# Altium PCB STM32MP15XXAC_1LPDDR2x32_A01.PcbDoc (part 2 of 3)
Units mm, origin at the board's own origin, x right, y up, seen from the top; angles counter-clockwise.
Board outline 89 x 120 mm, 6 copper layers (Top Layer, Signal Layer 1, Signal Layer 2, Signal Layer 3, Signal Layer 4, Bottom Layer), stack 1.556 mm thick; 87 components, 99 nets, 861 pads, 454 vias.
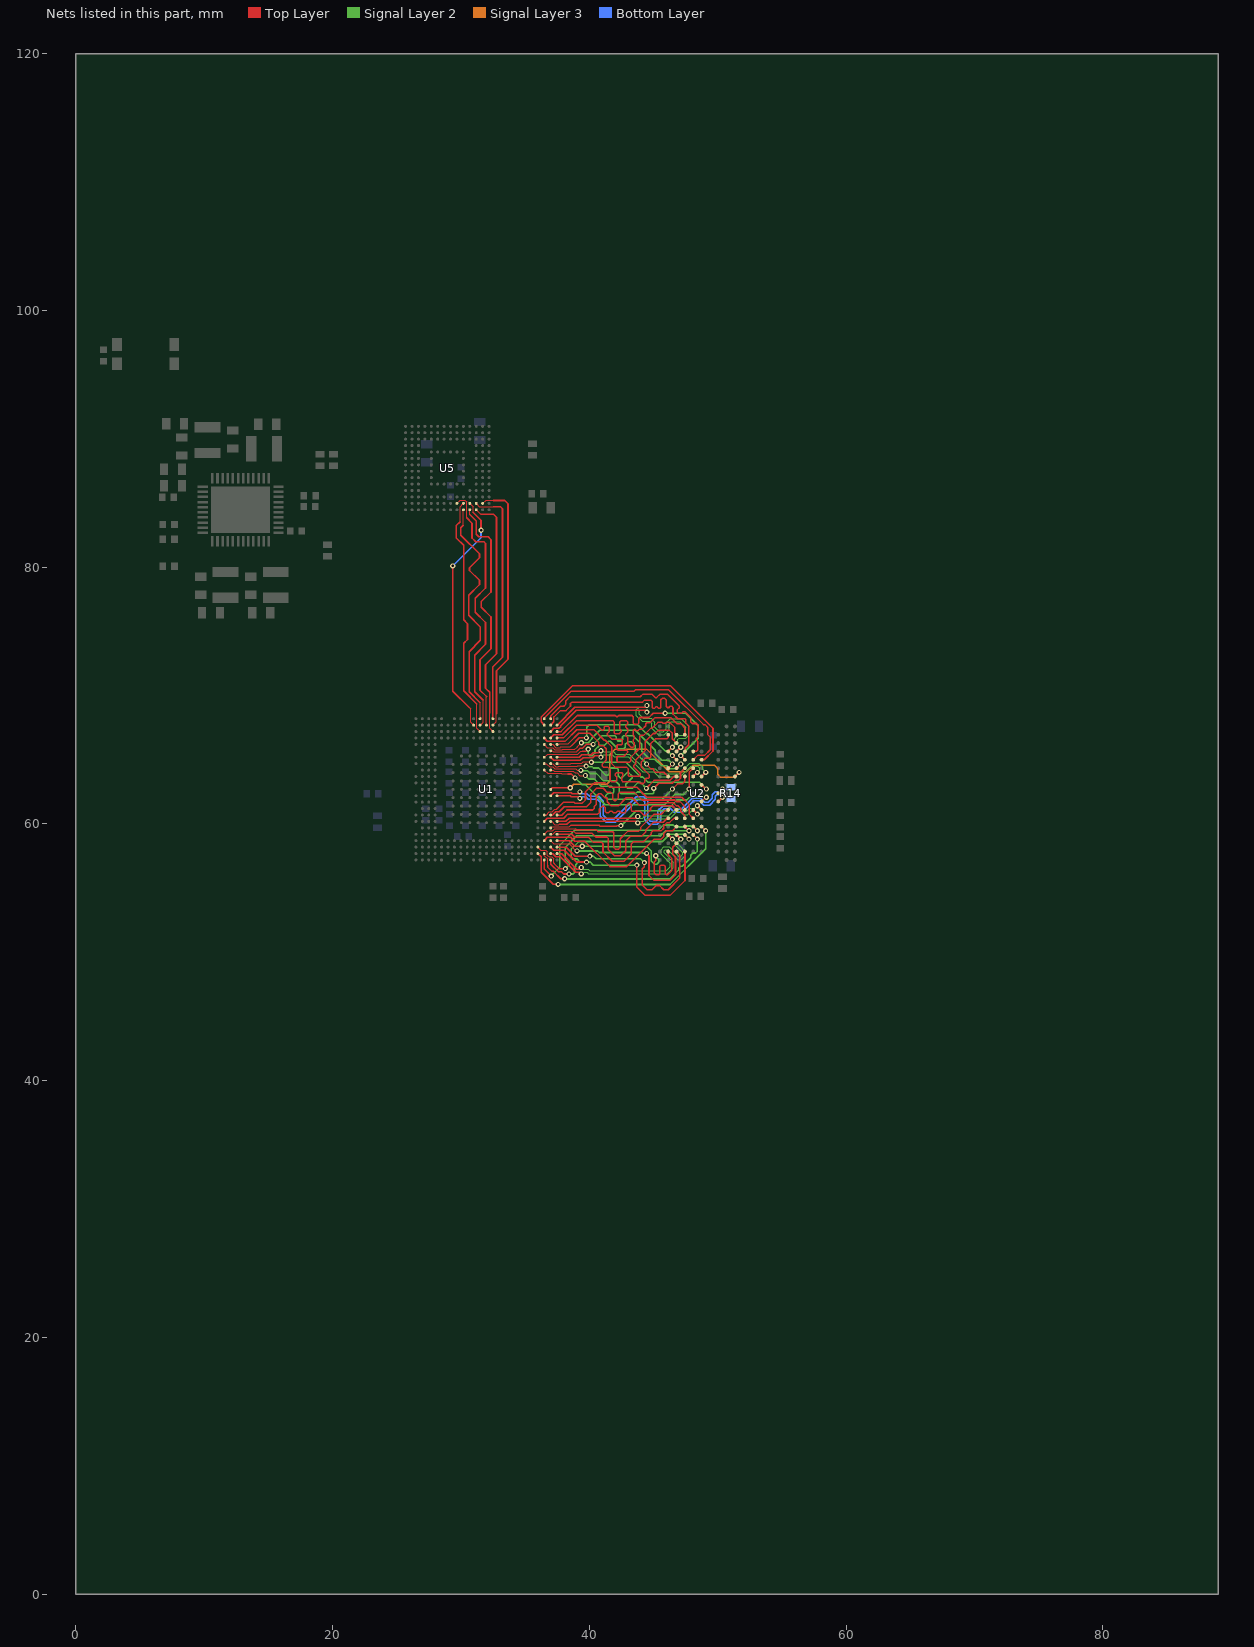
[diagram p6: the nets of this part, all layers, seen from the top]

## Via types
v1: diameter 0.4, hole 0.2, Top Layer to Bottom Layer, tented both sides, 265 vias
v2: diameter 0.6, hole 0.3, Top Layer to Bottom Layer, tented both sides, 102 vias
v3: diameter 0.25, hole 0.1, Top Layer to Signal Layer 1, tented top, 82 vias
v4: diameter 0.25, hole 0.1, Top Layer to Signal Layer 1, tented both sides, 5 vias

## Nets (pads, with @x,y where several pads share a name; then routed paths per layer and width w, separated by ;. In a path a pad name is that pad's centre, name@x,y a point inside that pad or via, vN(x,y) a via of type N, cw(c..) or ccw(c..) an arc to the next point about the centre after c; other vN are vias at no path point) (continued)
DDR_CLK_N: R14.2 U1.N23 U2.H3 | length 20
  Top Layer w0.1: U1.N23@37.5,62.2 38.521,62.2 38.591,62.13 39.141,62.13 v1(39.277,61.994) ; U2.H3@50.05,61.75 v1(50.375,62.075)
  Bottom Layer w0.1: v1@39.31,61.996 39.447,62.132 39.728,62.132 39.938,61.922 40.645,61.922 40.876,61.691 40.876,60.594 41.32,60.15 42.02,60.15 43.764,61.894 44.143,61.894 44.317,61.721 44.317,60.328 44.662,59.983 45.313,59.983 45.587,60.257 45.587,60.926 45.848,61.187 46.364,61.187 46.638,60.913 47.254,60.913 48.134,61.794 48.595,61.794 48.91,61.478 49.369,61.478 49.8,61.909 49.8,62.18 49.917,62.297 50.161,62.297 v1@50.377,62.081 ; v1@50.377,62.077 50.898,62.077 R14.2@51.025,61.95
DDR_CLK_P: R14.1 U1.N22 U2.J3 | length 20.7
  Top Layer w0.1: U1.N22@37,62.2 37.245,62.445 37.655,62.445 37.67,62.43 38.616,62.43 38.686,62.36 39.137,62.36 v1(39.277,62.5) ; U2.J3@50.05,62.4 v1(50.375,62.725)
  Bottom Layer w0.1: v1@39.281,62.504 39.422,62.362 39.823,62.362 40.027,62.159 40.733,62.159 41.106,61.786 41.106,60.689 41.415,60.38 41.925,60.38 43.669,62.124 44.238,62.124 44.547,61.816 44.547,60.424 44.757,60.213 45.218,60.213 45.357,60.352 45.357,61.022 45.753,61.417 46.46,61.417 46.734,61.143 47.159,61.143 48.039,62.024 48.69,62.024 49.006,61.708 49.274,61.708 49.57,62.004 49.57,62.275 49.822,62.527 50.174,62.527 50.373,62.725 v1(50.375,62.725) 50.9,62.725 R14.1@51.025,62.85
DDR_CSN: U1.M22 U2.L1 | length 19.5
  Top Layer w0.12: U1.M22@37,62.7 37.121,62.821 v1(38.521,62.821) v1@38.571,62.821 ; U2.L1@51.35,63.7 v1@51.667,64.017
  Signal Layer 3 w0.127: v1@38.518,62.813 38.523,62.819 38.799,63.094 41.364,63.094 41.592,63.322 41.592,65.4 42.025,65.834 44.462,65.834 46.236,64.059 47.582,64.059 48.106,64.583 49.751,64.583 50.008,64.326 50.008,63.867 50.221,63.654 51.311,63.654 v1@51.678,64.021
  other v1: 51.675,64.025
DDR_DQ0: U1.E22 U2.N8 | length 12.2
  Top Layer w0.09: U1.E22@37,66.2 37.154,66.2 37.399,65.955 37.725,65.955 37.8,66.03 38.535,66.03 38.615,66.11
  Top Layer w0.12: 38.631,66.11 39.231,66.71 v1(39.775,66.71) ; v1(46.475,65.325) U2.N8@46.8,65
  Signal Layer 2 w0.127: v1@39.804,66.71 39.804,67.535 40.003,67.733 ; 40.003,67.737 43.77,67.737 44.466,67.04 44.568,67.04 45.919,65.689 46.113,65.689 v1@46.476,65.326
DDR_DQ1: U1.F22 U2.M8 | length 13.2
  Top Layer w0.09: U1.F22@37,65.7 37.115,65.7 37.2,65.615 38.065,65.615 38.085,65.635 39.012,65.635 39.117,65.74
  Top Layer w0.12: 39.117,65.74 39.284,65.907 39.487,65.907 39.775,66.195 v1(40.3,66.195) ; U2.M8@46.8,64.35 v1(47.125,64.675)
  Signal Layer 2 w0.127: v1@40.302,66.196 40.99,66.884 41.992,66.884 42.095,66.78 42.095,66.621 42.247,66.469 42.479,66.469 42.591,66.582 42.591,66.783 42.693,66.884 43.412,66.884 43.725,66.571 ; 43.726,66.573 44.096,66.202 44.096,65.669 44.715,65.05 45.115,65.05 45.634,64.532 ; 45.634,64.533 46.054,64.533 46.277,64.311 46.768,64.311 47.128,64.671 v1@47.129,64.672
DDR_DQ2: U1.H21 U2.M7 | length 13.7
  Top Layer w0.09: U1.H21@36.5,64.7 36.654,64.7 36.909,64.445 37.168,64.445 37.328,64.285 37.672,64.285 37.692,64.305 38.945,64.305 39.075,64.175 v1(39.355,64.175)
  Top Layer w0.12: v1@45.02,62.773 45.023,62.776 45.416,63.17 46.47,63.17 46.69,63.39 46.928,63.39 47.11,63.571 47.11,64.01 U2.M7@47.45,64.35
  Signal Layer 2 w0.127: v1(39.355,64.175) 39.388,64.142 39.868,64.142 40.081,63.929 40.562,63.929 41.119,63.371 42.029,63.371 42.349,63.051 42.349,62.492 42.483,62.358 43.605,62.358 43.743,62.497 44.009,62.497 44.148,62.358 44.949,62.358 45.026,62.435 v1(45.025,62.775)
DDR_DQ3: U1.E21 U2.M9 | length 12.5
  Top Layer w0.09: U1.E21@36.5,66.2 36.75,65.95 ; 36.751,65.95 37.163,65.95 37.328,65.785 37.89,65.785 37.93,65.825 38.89,65.825 39.052,65.988
  Top Layer w0.12: 39.052,65.988 v1(39.395,66.33) ; U2.M9@46.16,64.35 46.48,64.67 v1@46.485,64.675
  Signal Layer 2 w0.127: v1@39.397,66.331 39.915,66.331 40.222,66.637 40.222,66.721 ; 40.231,66.729 40.813,67.311 43.591,67.311 45.149,65.753 45.149,65.486 45.674,64.961 45.975,64.961 46.199,64.962 46.481,64.681 v1@46.487,64.675
  other v1: 46.475,64.675
DDR_DQ4: U1.J21 U2.M6 | length 14.7
  Top Layer w0.09: U1.J21@36.5,64.2 36.755,63.945 37.82,63.945 37.87,63.895 38.335,63.895
  Top Layer w0.12: 38.335,63.895 38.6,63.895 v1@38.899,63.596 ; v1(47.775,62.725) 47.775,64.027 U2.M6@48.1,64.35 U2.M6@48.101,64.353
  Signal Layer 2 w0.127: v1@38.899,63.598 38.901,63.597 39.451,63.046 39.721,63.046 ; 39.724,63.04 41.26,61.504 45.869,61.504 46.663,62.299 47.349,62.299 v1(47.775,62.725) v1@47.776,62.725
  other v1: 38.9,63.596
DDR_DQ5: U1.J22 U2.L7 | length 13.9
  Top Layer w0.09: U1.J22@37,64.19 37.183,64.19 37.258,64.115 38.77,64.115 38.9,63.985 39.055,63.985 39.265,63.775 v1(39.7,63.775)
  Top Layer w0.12: v1@46.464,62.722 46.47,62.729 46.866,63.125 47.267,63.125 47.45,63.308 U2.L7@47.45,63.698
  Signal Layer 2 w0.127: v1@39.702,63.776 39.976,63.502 40.385,63.502 40.942,62.944 41.722,62.944 41.922,62.744 41.922,62.493 41.832,62.403 41.481,62.403 41.296,62.218 41.296,62.072 41.437,61.931 45.692,61.931 46.48,62.719 v1@46.486,62.725
  other v1: 46.475,62.725
DDR_DQ6: U1.H22 U2.L8 | length 13.9
  Top Layer w0.09: U1.H22@37,64.7 37.154,64.7 37.399,64.455 37.601,64.455 37.646,64.5 39.085,64.5 39.12,64.535 39.725,64.535 v1(39.755,64.505)
  Top Layer w0.12: v1@44.445,62.791 45.044,63.39 46.278,63.39 46.588,63.7 U2.L8@46.8,63.7
  Signal Layer 2 w0.127: v1(39.755,64.505) 39.814,64.447 40.25,64.447 40.335,64.362 ; 40.338,64.358 40.737,64.358 41.296,63.798 41.449,63.798 41.561,63.91 41.561,64.242 41.676,64.357 42.164,64.357 42.252,64.268 42.252,63.755 42.42,63.587 42.536,63.587 42.957,64.007 43.063,64.007 43.345,63.725 43.345,63.6 42.848,63.103 42.848,62.945 43.001,62.792 43.365,62.792 43.804,63.231 44.001,63.231 v1@44.447,62.785
  other v1: 44.45,62.775
DDR_DQ7: U1.G21 U2.L9 | length 13
  Top Layer w0.09: U1.G21@36.515,65.2 36.76,65.445 39.12,65.445 39.34,65.665 39.46,65.665
  Top Layer w0.12: 39.46,65.665 39.76,65.665 v1(39.925,65.83) ; v1@44.48,64.61 44.775,64.315 44.95,64.315 45.04,64.226 45.04,64.159 45.163,64.036 45.813,64.036 U2.L9@46.15,63.7
  Signal Layer 2 w0.127: v1@39.927,65.826 39.927,65.426 40.027,65.326 40.252,65.326 40.452,65.526 40.452,65.776 40.809,66.133 41.193,66.133 41.502,66.442 41.647,66.442 42.231,65.858 42.699,65.858 42.817,65.976 42.817,66.204 43.006,66.393 43.3,66.393 43.594,66.099 43.594,65.568 44.481,64.681 v1@44.487,64.675
  other v1: 44.475,64.675
DDR_DQ8: U1.T21 U2.F6 | length 14.7
  Top Layer w0.09: U1.T21@36.5,60.7 36.654,60.7 36.899,60.945 37.116,60.945 37.316,61.145 37.455,61.145 37.493,61.183
  Top Layer w0.12: 37.493,61.183 38.02,61.71 38.8,61.71 38.9,61.61 39.442,61.61 39.709,61.877 ; 39.711,61.878 39.711,62.511 ; 39.712,62.512 40.398,63.198 41.26,63.198 41.58,62.878 43.701,62.878 ; 43.699,62.878 44.487,62.09 47.197,62.09 ; 47.199,62.09 47.776,61.513 47.776,60.773 U2.F6@48.1,60.45
DDR_DQ9: U1.U21 U2.G8 | length 13.3
  Top Layer w0.1: U1.U21@36.5,60.2 36.75,60.45 38.01,60.45
  Top Layer w0.12: 38.01,60.45 38.33,60.77 40.666,60.77 40.799,60.903 ; 40.801,60.905 40.801,61.172 41.027,61.398 41.136,61.398 41.249,61.286 41.249,60.965 41.344,60.87 41.509,60.87 41.628,60.99 41.778,60.99 41.897,60.87 42.078,60.87 42.197,60.99 42.384,60.99 42.503,60.87 42.764,60.87 42.836,60.942 42.836,61.398 43.056,61.618 43.177,61.618 43.258,61.537 43.258,61.097 43.359,60.996 43.954,60.996 44.254,60.696 44.383,60.696 44.772,61.085 44.772,61.23 44.972,61.43 46.469,61.43 ; 46.47,61.43 U2.G8@46.8,61.1
DDR_DQ10: U1.T22 U2.G7 | length 13.5
  Top Layer w0.09: U1.T22@37,60.7 37.154,60.7
  Top Layer w0.1: 37.149,60.704 37.405,60.96 37.67,60.96
  Top Layer w0.12: 37.67,60.96 38.06,61.35 39.791,61.35 40.133,61.692 ; 40.131,61.704 40.131,62.336 40.573,62.778 41.086,62.778 41.406,62.458 41.691,62.458 41.819,62.331 41.819,61.961 41.95,61.83 42.079,61.83 42.246,61.996 42.246,62.329 42.375,62.458 43.525,62.458 44.113,61.87 46.65,61.87 ; 46.652,61.87 46.77,61.751 47.064,61.751 47.449,61.367 U2.G7@47.45,61.1
DDR_DQ11: U1.W21 U2.G9 | length 12.9
  Top Layer w0.09: U1.W21@36.5,59.2 36.755,59.455 37.168,59.455 37.328,59.615 38.94,59.615
  Top Layer w0.12: 38.94,59.615 38.995,59.56 40.525,59.56 40.678,59.407 41.826,59.407 41.915,59.318 41.915,58.169 42.042,58.043 42.284,58.043 42.421,58.18 42.421,58.843 43.026,59.449 43.871,59.449 44,59.577 44,59.719 45.039,60.758 ; 45.041,60.76 45.61,60.76 45.95,61.1 U2.G9@46.15,61.1
DDR_DQ12: U1.W23 U2.F8 | length 12.6
  Top Layer w0.1: U1.W23@37.5,59.2 38.635,59.2 38.875,58.96
  Top Layer w0.12: 38.875,58.96 39.937,58.96 40.33,58.567 40.971,58.567 41.075,58.462 41.075,57.816 41.787,57.104 42.715,57.104 43.261,57.65 43.261,58.415 43.455,58.609 44.219,58.609 44.84,59.229 44.84,59.348 44.952,59.46 45.264,59.46 45.598,59.46 ; 45.597,59.46 45.809,59.672 45.809,59.869 46.049,60.11 46.26,60.11 46.6,60.45 U2.F8@46.8,60.45
DDR_DQ13: U1.T23 U2.F7 | length 13
  Top Layer w0.1: U1.T23@37.5,60.7 37.875,60.7 38.03,60.855
  Top Layer w0.12: 38.03,60.855 38.265,61.09 40.273,61.09 40.381,61.198 40.381,61.346 40.553,61.518 40.553,62.163 40.747,62.358 40.912,62.358 41.232,62.038 41.323,62.038 41.399,61.962 41.399,61.73 41.719,61.41 42.255,61.41 42.882,62.037 43.351,62.038 43.939,61.45 44.395,61.45 44.595,61.65 46.558,61.65 ; 46.561,61.65 46.801,61.41 46.928,61.41 47.121,61.216 47.121,60.989 47.448,60.663 ; U2.F7@47.45,60.45 47.45,60.661
DDR_DQ14: U1.W22 U2.F9 | length 12.3
  Top Layer w0.09: U1.W22@37,59.2 37.154,59.2 37.399,59.445 38.8,59.445 38.965,59.28
  Top Layer w0.12: 38.965,59.28 40.211,59.28 40.504,58.987 41.375,58.987 41.495,58.866 41.495,57.99 41.961,57.524 42.442,57.524 42.841,57.923 42.841,58.669 43.2,59.029 44.045,59.029 44.42,59.403 44.42,59.545 45.01,60.135 45.764,60.135 46.077,60.448 46.15,60.448 U2.F9@46.174,60.448
DDR_DQ15: U1.Y21 U2.E8 | length 12.8
  Top Layer w0.1: U1.Y21@36.5,58.7 36.75,58.95 38.55,58.95 38.86,58.64
  Top Layer w0.12: 38.86,58.64 39.659,58.64 ; 39.659,58.638 41.613,56.684 42.924,56.684 ; 42.925,56.683 45.072,58.83 45.618,58.83 45.81,59.021 45.81,59.27 46.005,59.465 46.465,59.465 U2.E8@46.8,59.8
DDR_DQ16: U1.B22 U2.P7 | length 17
  Top Layer w0.1: U1.B22@37.003,67.703 37.25,67.95 37.25,68.34
  Top Layer w0.12: 37.25,68.34 37.761,68.838 38.199,68.838 38.543,69.182 38.543,69.391 38.652,69.5 44.152,69.5 44.302,69.65 44.8,69.65 44.9,69.551 44.9,69.099 44.992,69.007 45.083,69.007 45.197,69.121 45.295,69.121 45.409,69.007 45.518,69.007 45.579,69.067 45.579,69.67 45.709,69.8 45.86,69.8 46.007,69.654 46.007,69.141 46.075,69.073 46.221,69.073 46.313,69.164 46.427,69.164 46.526,69.065 46.526,68.568 ; 46.526,68.567 46.89,68.202 47.454,68.202 47.532,68.125 47.532,67.86 47.76,67.632 47.76,66.171 47.48,65.892 U2.P7@47.48,65.655
DDR_DQ17: U1.D22 U2.T7 | length 18
  Top Layer w0.1: U1.D22@37,66.7 37.25,66.95 37.66,66.95
  Top Layer w0.12: 37.66,66.95 37.905,66.95 38.984,68.029 ; 38.985,68.03 41.863,68.03 41.967,67.927 41.967,67.089 42.026,67.03 42.332,67.03 42.478,67.177 42.478,67.301 42.39,67.389 42.39,67.96 42.46,68.03 42.916,68.03 43.012,67.934 43.012,67.839 42.84,67.667 42.84,67.549 43.008,67.381 43.008,67.175 42.831,66.999 42.831,66.896 42.999,66.729 42.999,66.25 43.282,65.967 43.415,65.967 43.519,66.071 43.519,66.334 43.418,66.435 43.418,66.548 ; 43.42,66.552 43.519,66.65 43.519,66.827 43.42,66.926 43.42,67.278 43.503,67.361 43.588,67.361 43.69,67.259 43.772,67.259 ; 43.779,67.26 43.882,67.363 44.108,67.363 44.403,67.658 44.403,67.813 44.485,67.895 44.746,67.895 45.016,68.167 ; 45.015,68.168 45.114,68.267 46.374,68.267 ; 46.374,68.267 46.841,67.8 47.14,67.8 47.45,67.49 U2.T7@47.45,66.95
DDR_DQ18: U1.D23 U2.T8 | length 17.5
  Top Layer w0.12: U1.D23@37.5,66.7 38.007,66.7 38.983,67.675 40.622,67.675 40.981,67.317 41.082,67.317 ; 41.09,67.318 41.16,67.388 41.16,67.547 41.223,67.61 41.483,67.61 41.548,67.545 41.548,67.186 41.414,67.052 41.414,66.953 41.758,66.61 42.523,66.61 42.579,66.555 42.579,66.254 42.514,66.19 42.222,66.19 42.165,66.133 42.165,65.826 42.238,65.752 42.903,65.752 42.985,65.67 42.985,65.573 42.694,65.282 42.227,65.282 42.165,65.22 42.165,64.889 42.227,64.827 43.145,64.827 43.22,64.902 43.22,65.178 43.939,65.897 43.939,66.825 44.013,66.899 44.238,66.899 44.808,67.47 44.919,67.47 ; 44.918,67.471 45.358,67.915 45.681,67.915 45.764,67.832 ; 45.777,67.833 45.918,67.833 46.001,67.915 46.272,67.915 46.68,67.508 46.68,67.07 U2.T8@46.8,66.95
DDR_DQ19: U1.B21 U2.N5 | length 19.4
  Top Layer w0.1: 36.248,68.316 36.248,67.958 36.503,67.703 U1.B21@36.51,67.696
  Top Layer w0.12: 36.248,68.316 38.692,70.76 ; 38.698,70.76 46.334,70.76 49.642,67.452 49.642,65.68 48.961,64.999 U2.N5@48.752,64.999
DDR_DQ20: U1.A21 U2.N6 | length 18.3
  Top Layer w0.12: U1.A21@36.5,68.249 38.591,70.34 43.481,70.34 43.581,70.44 46.202,70.44 48.897,67.745 49.009,67.745 49.22,67.534 49.22,66.972 49.422,66.77 49.422,65.785 48.977,65.339 48.442,65.339 48.101,64.998 U2.N6@48.096,64.994
DDR_DQ21: U1.E23 U2.T9 | length 17.8
  Top Layer w0.09: U1.E23@37.5,66.2 37.67,66.2 37.72,66.25 38.365,66.25 38.433,66.318
  Top Layer w0.12: 38.433,66.318 39.185,67.07 40.039,67.07 40.727,66.383 ; 40.729,66.376 40.729,66.216 40.835,66.11 41.07,66.11 41.325,65.855 41.325,64.977 41.025,64.677 41.025,64.514 41.102,64.437 41.429,64.437 41.621,64.245 41.621,63.431 41.753,63.298 42.041,63.298 42.13,63.387 42.13,63.679 42.043,63.767 ; 42.041,63.767 42.041,63.913 42.116,63.987 42.531,63.987 42.605,63.913 42.605,63.735 42.549,63.679 42.549,63.361 42.612,63.298 43.875,63.298 44.019,63.154 44.214,63.154 44.335,63.275 44.335,63.452 44.445,63.562 44.622,63.562 44.688,63.628 44.688,63.807 44.06,64.436 44.06,64.83 44.335,65.105 44.682,65.105 44.779,65.202 ; 44.78,65.208 44.78,66.253 45.155,66.629 ; 45.158,66.63 46.044,66.63 46.151,66.737 ; 46.15,66.745 U2.T9@46.15,66.95
DDR_DQ22: U1.D21 U2.R8 | length 17.2
  Top Layer w0.1: U1.D21@36.5,66.7 36.75,66.45 37.69,66.45
  Top Layer w0.12: 37.69,66.455 38.15,66.455 39.035,67.34 40.356,67.34 ; 40.364,67.34 41.174,66.53 41.244,66.53 41.745,66.029 41.745,64.715 42.053,64.407 42.937,64.407 43.025,64.319 43.025,63.786 43.092,63.718 43.903,63.718 43.977,63.792 43.977,63.925 43.483,64.418 43.483,64.571 43.64,64.728 43.64,65.004 44.359,65.723 ; 44.359,65.725 44.359,66.427 44.982,67.05 45.134,67.05 ; 45.139,67.055 45.359,67.275 ; 45.368,67.286 46.251,67.286 46.46,67.078 46.46,66.64 U2.R8@46.8,66.3
DDR_DQ23: U1.A22 U2.P6 | length 17.1
  Top Layer w0.12: U1.A22@37,68.2 37,68.403 37.763,69.166 38.016,69.166 38.188,69.339 38.188,69.602 38.507,69.921 38.857,69.921 ; 38.818,69.92 43.978,69.92 ; 43.983,69.919 44.184,70.12 44.865,70.12 45.138,69.847 45.25,69.847 45.524,70.12 46.069,70.12 47.022,69.167 47.022,69.057 46.846,68.88 46.846,68.7 46.933,68.613 47.179,68.613 47.318,68.753 47.437,68.753 47.922,68.268 47.922,67.923 48.018,67.827 48.363,67.827 48.495,67.695 48.495,67.281 48.44,67.226 48.44,66.762 ; U2.P6@48.1,65.65 48.337,65.65 48.44,65.753 48.44,66.459 48.351,66.547 48.351,66.681 48.439,66.769
DDR_DQ24: U1.Y23 U2.B9 | length 15.6
  Top Layer w0.1: U1.Y23@37.5,58.7 38.455,58.7 38.885,58.27 v1(39.46,58.27)
  Top Layer w0.12: v1@45.177,57.529 45.177,57.525 45.177,57.159 45.078,57.059 45.078,56.163 45.184,56.057 45.435,56.057 45.502,56.124 45.502,56.72 45.582,56.8 45.831,56.8 45.921,56.71 45.921,56.126 45.99,56.057 46.112,56.057 46.44,56.385 46.44,57.32 46.15,57.61 U2.B9@46.15,57.85
  Signal Layer 2 w0.127: v1(39.46,58.27) 40.985,58.271 41.041,58.214 44.52,58.214 44.835,57.899 44.835,57.119 45.088,56.867 45.264,56.867 45.407,57.009 45.407,57.227 45.165,57.469 v1@45.165,57.511
  other v1: 45.18,57.525
DDR_DQ25: U1.Y22 U2.C8 | length 14.7
  Top Layer w0.09: U1.Y22@37,58.7 37.25,58.45 38.429,58.45 38.984,57.895 39.05,57.895 v1@39.056,57.895
  Top Layer w0.12: v1@44.47,57.71 44.658,57.522 44.658,55.988 ; 44.658,55.987 45.015,55.63 46.303,55.63 ; 46.304,55.631 46.722,56.048 46.722,57.45 46.51,57.662 46.51,58.187 46.797,58.475 46.797,58.5 U2.C8@46.797,58.516
  Signal Layer 2 w0.127: v1@39.057,57.896 40.658,57.896 40.77,57.784 ; 40.777,57.785 44.137,57.785 44.211,57.711 v1(44.465,57.71) v1@44.467,57.711
  other v1: 39.05,57.9
DDR_DQ26: U1.AB21 U2.D6 | length 15.7
  Top Layer w0.09: U1.AB21@36.5,57.7 36.5,57.545 36.755,57.29 36.755,56.77
  Top Layer w0.12: 36.755,56.77 36.755,56.66 37.11,56.305 37.22,56.305 37.787,55.738 v1@38.072,55.738 ; U2.D6@48.1,59.15 v1(48.425,58.825)
  Signal Layer 2 w0.127: v1@38.1,55.718 46.262,55.718 46.96,56.416 46.96,56.565 47.11,56.716 47.113,56.714 47.258,56.714 47.906,57.361 47.906,57.575 48.07,57.739 48.283,57.739 48.429,57.884 48.429,58.825 v1@48.429,58.864
  other v1: 38.08,55.735
DDR_DQ27: U1.AB20 U2.E5 | length 17.8
  Top Layer w0.1: U1.AB20@36,57.7 36.25,57.45 36.25,56.245 37.199,55.296 v1@37.567,55.296
  Top Layer w0.12: U2.E5@48.75,59.8 v1@49.066,59.484
  Signal Layer 2 w0.127: v1@37.588,55.291 46.298,55.291 ; 46.298,55.292 49.067,58.061 v1@49.067,59.472
  other v1: 37.581,55.294 49.065,59.475
DDR_DQ28: U1.AC22 U2.D7 | length 15.2
  Top Layer w0.12: 37,56.874 37.599,56.275 37.85,56.275 38.02,56.105 v1(38.425,56.105) ; 37,56.88 U1.AC22@37,57.2 ; U2.D7@47.45,59.15 v1(47.775,58.825)
  Signal Layer 2 w0.127: v1@38.427,56.106 38.747,56.106 38.853,56.213 38.853,56.603 ; 38.61,57.371 38.61,58.053 39.198,58.641 45.704,58.641 ; 38.613,57.366 38.703,57.275 39.083,57.275 39.169,57.189 39.169,57.056 38.948,56.836 38.948,56.698 38.857,56.606 ; 45.716,58.649 46.274,59.207 ; 46.275,59.207 47.392,59.207 v1@47.753,58.846
DDR_DQ29: U1.AC21 U2.E6 | length 16.2
  Top Layer w0.12: U1.AC21@36.5,57.2 36.5,56.49 v1(37.045,55.945) ; U2.E6@48.1,59.8 v1(48.425,59.475)
  Signal Layer 2 w0.127: v1@37.022,55.948 37.032,55.958 37.72,56.646 37.72,58.37 38.855,59.506 45.364,59.506 45.782,59.924 46.54,59.924 46.697,59.766 47.276,59.766 47.349,59.839 48.06,59.839 v1@48.418,59.481
DDR_DQ30: U1.AA23 U2.B8 | length 15
  Top Layer w0.1: U1.AA23@37.5,58.2 38.215,58.2 38.917,57.498
  Top Layer w0.12: 38.917,57.498 v1@40.044,57.498 ; v1(44.298,56.989) 44.296,56.676 44.132,56.512 44.132,55.245 44.497,54.88 44.897,54.88 45.227,55.21 45.483,55.21 45.813,54.88 46.149,54.88 ; 46.149,54.882 47.042,55.774 47.042,57.619 U2.B8@46.812,57.849
  Signal Layer 2 w0.127: v1@40.057,57.496 40.339,57.496 40.538,57.297 43.987,57.297 v1(44.298,56.989) v1@44.305,56.979
  other v1: 40.055,57.495
DDR_DQ31: U1.AA22 U2.B7 | length 15.7
  Top Layer w0.1: U1.AA22@37,58.2 37.25,57.95 38.075,57.95 38.983,57.042
  Top Layer w0.12: 38.983,57.042 v1@39.789,57.042 ; v1@43.712,56.788 43.712,55.071 44.323,54.46 46.323,54.46 47.462,55.598 U2.B7@47.462,57.818
  Signal Layer 2 w0.127: v1@39.792,57.036 40.071,57.036 40.31,56.797 v1@43.713,56.797
  other v1: 43.716,56.794 39.79,57.035
DDR_DQM0: U1.H23 U2.K5 | length 13.1
  Top Layer w0.09: U1.H23@37.5,64.7 38.56,64.7 38.6,64.74 39.42,64.74 39.535,64.855 40.12,64.855 v1(40.165,64.81)
  Top Layer w0.12: U2.K5@48.75,63.05 49.078,62.721 49.13,62.721 v1@49.133,62.721
  Signal Layer 2 w0.127: v1@40.167,64.811 42.863,64.811 44.014,63.659 44.176,63.659 44.574,63.262 48.592,63.262 v1(49.13,62.725) v1@49.135,62.719
DDR_DQM1: U1.V22 U2.H5 | length 13.7
  Top Layer w0.09: U1.V22@37,59.7 37.085,59.785 38.43,59.785 38.544,59.899
  Top Layer w0.12: 38.544,59.899 40.777,59.899 40.85,59.827 42.12,59.827 42.169,59.876 42.465,59.876 v1@42.475,59.876 ; U2.H5@48.75,61.75 49.089,62.089 49.13,62.089 v1@49.137,62.089
  Signal Layer 2 w0.127: v1@42.47,59.846 42.484,59.86 43.664,61.04 46.009,61.04 46.84,61.872 47.593,61.872 47.804,62.082 v1@49.13,62.082
  other v1: 42.465,59.88 49.13,62.085
DDR_DQM2: U1.C23 U2.N7 | length 16.4
  Top Layer w0.12: U1.C23@37.5,67.2 37.813,67.2 39.063,68.45 ; 39.065,68.45 42.039,68.45 42.117,68.373 42.208,68.373 42.286,68.45 43.336,68.45 43.432,68.354 43.432,67.86 43.508,67.783 43.787,67.783 43.871,67.867 43.871,67.99 43.871,68.232 43.933,68.294 ; 43.938,68.295 44.654,68.295 44.984,68.626 v1@45.898,68.626 ; v1@47.14,65.31 U2.N7@47.45,65
  Signal Layer 2 w0.127: v1@45.907,68.617 47.516,68.617 48.49,67.643 48.49,66.689 v1@47.126,65.325
  other v1: 47.125,65.325 45.906,68.628
DDR_DQM3: U1.AA20 U2.E7 | length 15.7
  Top Layer w0.09: U1.AA20@36,58.2 36.245,57.955 36.625,57.955 36.75,57.83 36.75,57.575 36.875,57.45 37.096,57.45 37.245,57.301 37.245,56.93
  Top Layer w0.12: 37.26,56.925 37.66,56.525 v1(38.145,56.525) ; U2.E7@47.45,59.791 v1@47.763,59.478
  Signal Layer 2 w0.127: v1@38.147,56.526 38.442,56.821 38.442,56.932 38.147,57.227 38.147,58.194 39.032,59.079 45.541,59.079 45.948,59.486 47.771,59.486 v1@47.773,59.484
  other v1: 47.775,59.475
DDR_DQS0_N: U1.G23 U2.L5 | length 13.7
  Top Layer w0.1: U1.G23@37.5,65.2 39.22,65.2 39.425,65.405 40.16,65.405 40.315,65.56 40.733,65.56 v1@40.873,65.7 ; U2.L5@48.75,63.7 v1(49.075,64.025)
  Signal Layer 2 w0.09: v1(40.905,65.71) 41.017,65.711 41.117,65.611 41.901,65.611 42.062,65.449 43.127,65.449 44.276,64.3 45.126,64.3 45.523,63.903 47.002,63.903 47.839,64.74 48.548,64.74 48.846,64.442 48.846,64.255 v1@49.076,64.026
DDR_DQS0_P: U1.G22 U2.L6 | length 14
  Top Layer w0.1: U1.G22@37,65.2 37.25,64.95 37.604,64.95 37.624,64.97 39.315,64.97 39.52,65.175 40.265,65.175 40.42,65.33 40.79,65.33 v1(40.915,65.205) ; U2.L6@48.1,63.7 v1(48.425,64.025)
  Signal Layer 2 w0.09: v1@40.928,65.195 41.114,65.381 41.805,65.381 41.967,65.219 43.032,65.219 44.184,64.068 45.034,64.068 45.428,63.673 47.097,63.673 47.934,64.51 48.453,64.51 48.616,64.347 48.616,64.215 v1@48.426,64.025
DDR_DQS1_N: U1.U23 U2.G5 | length 12.2
  Top Layer w0.1: U1.U23@37.5,60.2 38.175,60.2 38.435,60.46 43.658,60.46 43.781,60.583 v1@43.784,60.586 ; v1(48.425,61.425) U2.G5@48.75,61.1
  Signal Layer 2 w0.09: v1@43.797,60.59 43.932,60.454 44.152,60.454 44.33,60.632 46.178,60.632 46.767,61.22 47.129,61.22 47.405,60.944 47.568,60.944 47.838,61.215 ; 47.838,61.22 48.221,61.22 v1@48.425,61.424
  other v1: 43.78,60.585
DDR_DQS1_P: U1.U22 U2.G6 | length 12.9
  Top Layer w0.09: U1.U22@37,60.2 37.088,60.2 37.333,59.955 37.635,59.955 37.65,59.97
  Top Layer w0.1: 37.65,59.97 38.27,59.97 38.53,60.23 43.631,60.23 v1@43.778,60.083 ; U2.G6@48.1,61.1 v1(48.425,60.775)
  Signal Layer 2 w0.09: v1@43.787,60.074 43.789,60.075 43.937,60.224 44.247,60.224 44.425,60.402 46.273,60.402 46.862,60.99 47.034,60.99 47.31,60.714 47.663,60.714 47.939,60.99 48.211,60.99 v1@48.426,60.776
  other v1: 43.78,60.085
DDR_DQS2_N: U1.B23 U2.P9 | length 17.3
  Top Layer w0.1: U1.B23@37.5,67.7 38.89,69.09 44.353,69.09 v1(44.492,69.23) ; U2.P9@46.15,65.65 v1(46.475,65.975)
  Signal Layer 2 w0.09: v1@44.481,69.226 44.348,69.093 43.891,69.093 43.682,68.885 43.682,68.44 44.122,68 44.725,68 44.883,67.842 44.883,67.442 45.375,66.95 45.85,66.95 46.23,67.33 46.23,67.805 46.402,67.977 47.068,67.977 47.525,67.52 47.525,67.025 47.424,66.924 46.914,66.924 46.676,66.686 46.676,66.175 v1@46.476,65.975
DDR_DQS2_P: U1.C22 U2.P8 | length 17.6
  Top Layer w0.1: U1.C22@37,67.2 37.25,67.45 37.632,67.45 37.77,67.588 37.77,67.645 38.986,68.86 44.355,68.86 v1(44.495,68.72) ; U2.P8@46.8,65.65 v1(47.125,65.975)
  Signal Layer 2 w0.09: v1@44.479,68.727 44.342,68.863 43.986,68.863 43.913,68.79 43.913,68.535 44.217,68.23 44.82,68.23 45.113,67.937 45.113,67.538 45.47,67.18 45.755,67.18 46,67.425 46,67.9 46.307,68.207 47.163,68.207 47.755,67.615 47.755,66.93 47.519,66.694 47.009,66.694 46.906,66.591 46.906,66.175 v1@47.106,65.975
DDR_DQS3_N: U1.AB23 U2.D9 | length 15.3
  Top Layer w0.1: U1.AB23@37.515,57.685 37.85,57.685 39.046,56.49 39.26,56.49 v1(39.38,56.61) ; U2.D9@46.15,59.15 v1(46.475,58.825)
  Signal Layer 2 w0.09: v1@39.374,56.611 39.378,56.608 39.516,56.469 39.926,56.469 40.039,56.356 45.998,56.356 46.312,56.671 46.312,56.937 45.598,57.651 45.598,58.002 45.817,58.221 46.232,58.221 46.997,57.456 47.088,57.456 47.267,57.635 47.267,57.758 46.696,58.329 46.696,58.615 v1@46.486,58.825
DDR_DQS3_P: U1.AB22 U2.D8 | length 16.3
  Top Layer w0.1: U1.AB22@37,57.7 37.146,57.7 37.396,57.45 37.76,57.45 38.951,56.26 39.232,56.26 v1@39.378,56.114 ; U2.D8@46.8,59.15 v1(47.125,58.825)
  Signal Layer 2 w0.09: v1(39.38,56.11) 39.509,56.239 39.831,56.239 39.944,56.126 46.093,56.126 46.542,56.575 46.542,57.032 45.828,57.746 45.828,57.907 45.913,57.991 46.136,57.991 46.902,57.226 47.184,57.226 47.497,57.54 47.497,57.854 46.926,58.425 46.926,58.625 v1(47.125,58.825) v1@47.126,58.825
eMMC_SDIO2_D0: U1.C13 U5.A3 | length 19.1
  Top Layer w0.09: U5.A3@31.2,84.475 31.55,84.125 ; 32.25,68.625 32.25,67.45 U1.C13@32.5,67.2
  Top Layer w0.13: 31.55,84.125 32.55,84.125 32.775,83.9 32.775,73.25 31.925,72.4 31.925,70.575 32.25,70.25 32.25,68.625
eMMC_SDIO2_D1: U1.B12 U5.A4 | length 19.1
  Top Layer w0.09: 30.7,84.1 U5.A4@30.7,84.475 ; U1.B12@32,67.7 32,69.925
  Top Layer w0.13: 30.7,84.1 31.2,83.6 31.2,82.575 31.4,82.375 32.125,82.375 32.35,82.15 32.35,78.075 31.6,77.325 31.6,76.875 32.35,76.125 32.35,73.65 31.5,72.8 31.5,70.425 32,69.925
eMMC_SDIO2_D2: U1.A11 U5.A5 | length 19
  Top Layer w0.09: 30.2,83.275 U5.A5@30.2,84.475 ; U1.A11@31.5,68.2 31.5,69.45
  Top Layer w0.13: 30.2,83.275 30,83.075 30,82.5 31.45,81.05 31.45,80.725 30.675,79.95 30.675,79.75 31.45,78.975 31.45,78.65 30.625,77.825 30.625,76.25 31.525,75.35 31.525,74.3 30.65,73.425 30.65,70.3 31.5,69.45
eMMC_SDIO2_D3: U1.B13 U5.B2 | length 19.9
  Top Layer w0.09: U5.B2@31.7,84.975 31.725,84.975 31.965,85.215 32.51,85.215 32.525,85.2 ; U1.B13@32.5,67.7 32.75,67.95 32.75,68.6 ; 33.4,85.2 33.425,85.2
  Top Layer w0.13: 32.525,85.2 33.4,85.2 ; 32.775,68.6 32.775,71.941 33.675,72.841 33.675,84.95 33.425,85.2
eMMC_SDIO2_D4: U1.A13 U5.B3 | length 18.9
  Top Layer w0.09: U5.B3@31.2,84.975 31.2,84.965 31.45,84.715 32.515,84.715
  Top Layer w0.13: U1.A13@32.5,68.2 32.5,72.25 33.25,73 33.25,84.55 33.085,84.715 32.515,84.715
eMMC_SDIO2_D5: U1.B10 U5.B4 | length 19.2
  Top Layer w0.09: 30.65,69.075 30.76,68.965 30.76,67.94 U1.B10@31,67.7 ; U5.B4@30.7,84.975 30.95,84.725 30.95,84.275
  Top Layer w0.13: v1(29.375,80.1) 29.375,70.35 30.65,69.075 ; 30.95,84.275 31.575,83.65 v1(31.575,82.875)
  Bottom Layer w0.13: v1(29.375,80.1) 31.575,82.3 v1(31.575,82.875)
eMMC_SDIO2_D6: U1.C11 U5.B5 | length 19
  Top Layer w0.09: 29.95,83.55 29.95,84.725 U5.B5@30.2,84.975 U5.B5@30.2,84.965 ; 31.25,69.35 31.25,67.45 U1.C11@31.5,67.2
  Top Layer w0.13: 29.95,83.55 29.65,83.25 29.65,82.275 30.225,81.7 30.225,75.9 30.525,75.6 30.525,74.375 30.225,74.075 30.225,70.375 31.25,69.35
eMMC_SDIO2_D7: U1.B11 U5.B6 | length 20.7
  Top Layer w0.09: U5.B6@29.7,84.975 29.95,85.225 30.325,85.225 30.45,85.1 30.45,83.85 ; U1.B11@31.5,67.7 31.74,67.94 31.74,69.635
  Top Layer w0.13: 30.45,83.85 30.875,83.425 30.875,82.275 31.175,81.975 31.8,81.975 31.925,81.85 31.925,78.375 31.125,77.575 31.125,76.5 31.925,75.7 31.925,74 31.075,73.15 31.075,70.3 31.74,69.635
